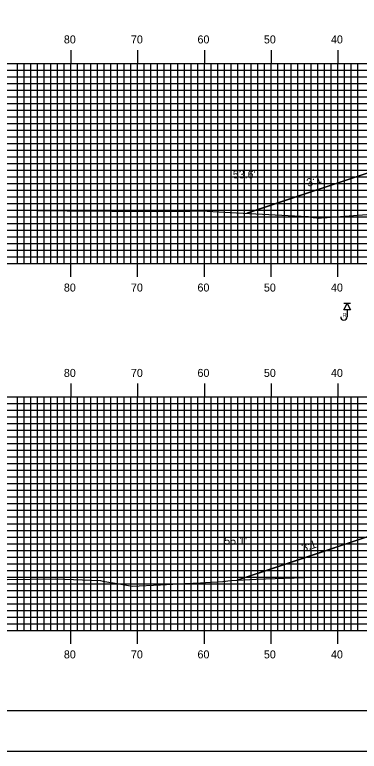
# Model space of a CAD drawing. Extents: x 1763365 to 1763708, y 442591 to 442811.
# Drawn here: x 1763442.4 to 1763494, y 442590.5 to 442701 of the extents above; entities that cross this region are included whole.
import ezdxf

# ---------------------------------------------------------------- set-up
doc = ezdxf.new("R2010")
doc.units = 0
for name, color, linetype in [('ANNOTATION', 7, 'Continuous'), ('BORDER', 7, 'Continuous'), ('BORING - REFUSAL', 7, 'Continuous'), ('D_Roadway_Centerline', 7, 'Continuous'), ('D_Roadway_SlopeLines', 7, 'Continuous'), ('D_Text_Standard', 7, 'Continuous'), ('H_V ANNOTATION', 7, 'Continuous'), ('MAJOR', 7, 'Continuous'), ('MINOR', 7, 'Continuous'), ('PLOT BOUNDARY', 7, 'Continuous'), ('S_Roadway_Centerline', 7, 'Continuous')]:
    doc.layers.add(name, color=color, linetype=linetype)

msp = doc.modelspace()

# ---------------------------------------------------------------- linework, layer by layer
at = {"layer": 'BORDER'}
msp.add_lwpolyline([(1763381.21, 442596.67), (1763701.21, 442596.67), (1763701.21, 442806.67), (1763381.21, 442806.67)], close=True, dxfattribs=at)
at = {"layer": 'BORING - REFUSAL'}
for p, q in [((1763492.69, 442657.7), (1763491.73, 442657.7)), ((1763492.21, 442656.74), (1763492.21, 442655.68))]:
    msp.add_line(p, q, dxfattribs=at)
msp.add_lwpolyline([(1763492.21, 442657.7), (1763492.69, 442656.74), (1763491.73, 442656.74)], close=True, dxfattribs=at)
msp.add_arc((1763491.72, 442655.68), 0.485, 180, 0, dxfattribs=at)
at = {"layer": 'D_Roadway_Centerline'}
for points in [[(1763477.18, 442671.2), (1763477.21, 442671.21), (1763498.81, 442678.4), (1763499.23, 442678.51), (1763499.27, 442678.52), (1763510.81, 442681.4), (1763510.81, 442681.4), (1763518.81, 442681.72), (1763519.87, 442681.76), (1763530.81, 442682.16), (1763541.63, 442682.55), (1763542.81, 442682.59), (1763550.81, 442682.27), (1763560.98, 442679.72), (1763562.81, 442679.27), (1763562.81, 442679.27), (1763576.24, 442675.91)], [(1763475.72, 442616.21), (1763481.91, 442618.27), (1763498.81, 442623.9), (1763499.25, 442624.01), (1763499.27, 442624.02), (1763502.08, 442624.72), (1763510.81, 442626.9), (1763518.81, 442627.22), (1763530.81, 442627.66), (1763542.81, 442628.09), (1763550.81, 442627.77), (1763553, 442627.22), (1763560.98, 442625.22), (1763560.98, 442625.22), (1763562.81, 442624.77), (1763562.81, 442624.77), (1763577.46, 442621.1)]]:
    msp.add_lwpolyline(points, dxfattribs=at)
at = {"layer": 'D_Roadway_SlopeLines'}
for points in [[(1763510.81, 442681.4), (1763498.81, 442678.4), (1763477.18, 442671.2)], [(1763510.81, 442626.9), (1763498.81, 442623.9), (1763475.72, 442616.21)]]:
    msp.add_lwpolyline(points, dxfattribs=at)
at = {"layer": 'MAJOR'}
for p, q in [((1763450.81, 442695.67), (1763450.81, 442693.67)), ((1763460.81, 442695.67), (1763460.81, 442693.67)), ((1763470.81, 442695.67), (1763470.81, 442693.67)), ((1763480.81, 442695.67), (1763480.81, 442693.67)), ((1763490.81, 442695.67), (1763490.81, 442693.67)), ((1763390.81, 442693.67), (1763670.81, 442693.67)), ((1763390.81, 442693.67), (1763670.81, 442693.67)), ((1763450.81, 442663.67), (1763450.81, 442693.67)), ((1763460.81, 442663.67), (1763460.81, 442693.67)), ((1763470.81, 442663.67), (1763470.81, 442693.67)), ((1763480.81, 442663.67), (1763480.81, 442693.67)), ((1763490.81, 442663.67), (1763490.81, 442693.67)), ((1763390.81, 442688.67), (1763670.81, 442688.67)), ((1763390.81, 442683.67), (1763670.81, 442683.67)), ((1763390.81, 442678.67), (1763670.81, 442678.67)), ((1763390.81, 442673.67), (1763670.81, 442673.67)), ((1763390.81, 442668.67), (1763670.81, 442668.67)), ((1763390.81, 442663.67), (1763670.81, 442663.67)), ((1763390.81, 442663.67), (1763670.81, 442663.67)), ((1763450.81, 442661.66), (1763450.81, 442663.67)), ((1763460.81, 442661.66), (1763460.81, 442663.67)), ((1763470.81, 442661.66), (1763470.81, 442663.67)), ((1763480.81, 442661.66), (1763480.81, 442663.67)), ((1763490.81, 442661.66), (1763490.81, 442663.67)), ((1763450.81, 442645.67), (1763450.81, 442643.67)), ((1763460.81, 442645.67), (1763460.81, 442643.67)), ((1763470.81, 442645.67), (1763470.81, 442643.67)), ((1763480.81, 442645.67), (1763480.81, 442643.67)), ((1763490.81, 442645.67), (1763490.81, 442643.67)), ((1763390.81, 442643.67), (1763670.81, 442643.67)), ((1763390.81, 442643.67), (1763670.81, 442643.67)), ((1763450.81, 442608.67), (1763450.81, 442643.67)), ((1763460.81, 442608.67), (1763460.81, 442643.67)), ((1763470.81, 442608.67), (1763470.81, 442643.67)), ((1763480.81, 442608.67), (1763480.81, 442643.67)), ((1763490.81, 442608.67), (1763490.81, 442643.67)), ((1763390.81, 442638.67), (1763670.81, 442638.67)), ((1763390.81, 442633.67), (1763670.81, 442633.67)), ((1763390.81, 442628.67), (1763670.81, 442628.67)), ((1763390.81, 442623.67), (1763670.81, 442623.67)), ((1763390.81, 442618.67), (1763670.81, 442618.67)), ((1763390.81, 442613.67), (1763670.81, 442613.67)), ((1763390.81, 442608.67), (1763670.81, 442608.67)), ((1763390.81, 442608.67), (1763670.81, 442608.67)), ((1763450.81, 442606.66), (1763450.81, 442608.67)), ((1763460.81, 442606.66), (1763460.81, 442608.67)), ((1763470.81, 442606.66), (1763470.81, 442608.67)), ((1763480.81, 442606.66), (1763480.81, 442608.67)), ((1763490.81, 442606.66), (1763490.81, 442608.67))]:
    msp.add_line(p, q, dxfattribs=at)
at = {"layer": 'MINOR'}
for p, q in [((1763442.81, 442663.67), (1763442.81, 442693.67)), ((1763443.81, 442663.67), (1763443.81, 442693.67)), ((1763444.81, 442663.67), (1763444.81, 442693.67)), ((1763445.81, 442663.67), (1763445.81, 442693.67)), ((1763446.81, 442663.67), (1763446.81, 442693.67)), ((1763447.81, 442663.67), (1763447.81, 442693.67)), ((1763448.81, 442663.67), (1763448.81, 442693.67)), ((1763449.81, 442663.67), (1763449.81, 442693.67)), ((1763451.81, 442663.67), (1763451.81, 442693.67)), ((1763452.81, 442663.67), (1763452.81, 442693.67)), ((1763453.81, 442663.67), (1763453.81, 442693.67)), ((1763454.81, 442663.67), (1763454.81, 442693.67)), ((1763455.81, 442663.67), (1763455.81, 442693.67)), ((1763456.81, 442663.67), (1763456.81, 442693.67)), ((1763457.81, 442663.67), (1763457.81, 442693.67)), ((1763458.81, 442663.67), (1763458.81, 442693.67)), ((1763459.81, 442663.67), (1763459.81, 442693.67)), ((1763461.81, 442663.67), (1763461.81, 442693.67)), ((1763462.81, 442663.67), (1763462.81, 442693.67)), ((1763463.81, 442663.67), (1763463.81, 442693.67)), ((1763464.81, 442663.67), (1763464.81, 442693.67)), ((1763465.81, 442663.67), (1763465.81, 442693.67)), ((1763466.81, 442663.67), (1763466.81, 442693.67)), ((1763467.81, 442663.67), (1763467.81, 442693.67)), ((1763468.81, 442663.67), (1763468.81, 442693.67)), ((1763469.81, 442663.67), (1763469.81, 442693.67)), ((1763471.81, 442663.67), (1763471.81, 442693.67)), ((1763472.81, 442663.67), (1763472.81, 442693.67)), ((1763473.81, 442663.67), (1763473.81, 442693.67)), ((1763474.81, 442663.67), (1763474.81, 442693.67)), ((1763475.81, 442663.67), (1763475.81, 442693.67)), ((1763476.81, 442663.67), (1763476.81, 442693.67)), ((1763477.81, 442663.67), (1763477.81, 442693.67)), ((1763478.81, 442663.67), (1763478.81, 442693.67)), ((1763479.81, 442663.67), (1763479.81, 442693.67)), ((1763481.81, 442663.67), (1763481.81, 442693.67)), ((1763482.81, 442663.67), (1763482.81, 442693.67)), ((1763483.81, 442663.67), (1763483.81, 442693.67)), ((1763484.81, 442663.67), (1763484.81, 442693.67)), ((1763485.81, 442663.67), (1763485.81, 442693.67)), ((1763486.81, 442663.67), (1763486.81, 442693.67)), ((1763487.81, 442663.67), (1763487.81, 442693.67)), ((1763488.81, 442663.67), (1763488.81, 442693.67)), ((1763489.81, 442663.67), (1763489.81, 442693.67)), ((1763491.81, 442663.67), (1763491.81, 442693.67)), ((1763492.81, 442663.67), (1763492.81, 442693.67)), ((1763493.81, 442663.67), (1763493.81, 442693.67)), ((1763390.81, 442692.67), (1763670.81, 442692.67)), ((1763390.81, 442691.67), (1763670.81, 442691.67)), ((1763390.81, 442690.67), (1763670.81, 442690.67)), ((1763390.81, 442689.67), (1763670.81, 442689.67)), ((1763390.81, 442687.67), (1763670.81, 442687.67)), ((1763390.81, 442686.67), (1763670.81, 442686.67)), ((1763390.81, 442685.67), (1763670.81, 442685.67)), ((1763390.81, 442684.67), (1763670.81, 442684.67)), ((1763390.81, 442682.67), (1763670.81, 442682.67)), ((1763390.81, 442681.67), (1763670.81, 442681.67)), ((1763390.81, 442680.67), (1763670.81, 442680.67)), ((1763390.81, 442679.67), (1763670.81, 442679.67)), ((1763390.81, 442677.67), (1763670.81, 442677.67)), ((1763390.81, 442676.67), (1763670.81, 442676.67)), ((1763390.81, 442675.67), (1763670.81, 442675.67)), ((1763390.81, 442674.67), (1763670.81, 442674.67)), ((1763390.81, 442672.67), (1763670.81, 442672.67)), ((1763390.81, 442671.67), (1763670.81, 442671.67)), ((1763390.81, 442670.67), (1763670.81, 442670.67)), ((1763390.81, 442669.67), (1763670.81, 442669.67)), ((1763390.81, 442667.67), (1763670.81, 442667.67)), ((1763390.81, 442666.67), (1763670.81, 442666.67)), ((1763390.81, 442665.67), (1763670.81, 442665.67)), ((1763390.81, 442664.67), (1763670.81, 442664.67)), ((1763442.81, 442608.67), (1763442.81, 442643.67)), ((1763443.81, 442608.67), (1763443.81, 442643.67)), ((1763444.81, 442608.67), (1763444.81, 442643.67)), ((1763445.81, 442608.67), (1763445.81, 442643.67)), ((1763446.81, 442608.67), (1763446.81, 442643.67)), ((1763447.81, 442608.67), (1763447.81, 442643.67)), ((1763448.81, 442608.67), (1763448.81, 442643.67)), ((1763449.81, 442608.67), (1763449.81, 442643.67)), ((1763451.81, 442608.67), (1763451.81, 442643.67)), ((1763452.81, 442608.67), (1763452.81, 442643.67)), ((1763453.81, 442608.67), (1763453.81, 442643.67)), ((1763454.81, 442608.67), (1763454.81, 442643.67)), ((1763455.81, 442608.67), (1763455.81, 442643.67)), ((1763456.81, 442608.67), (1763456.81, 442643.67)), ((1763457.81, 442608.67), (1763457.81, 442643.67)), ((1763458.81, 442608.67), (1763458.81, 442643.67)), ((1763459.81, 442608.67), (1763459.81, 442643.67)), ((1763461.81, 442608.67), (1763461.81, 442643.67)), ((1763462.81, 442608.67), (1763462.81, 442643.67)), ((1763463.81, 442608.67), (1763463.81, 442643.67)), ((1763464.81, 442608.67), (1763464.81, 442643.67)), ((1763465.81, 442608.67), (1763465.81, 442643.67)), ((1763466.81, 442608.67), (1763466.81, 442643.67)), ((1763467.81, 442608.67), (1763467.81, 442643.67)), ((1763468.81, 442608.67), (1763468.81, 442643.67)), ((1763469.81, 442608.67), (1763469.81, 442643.67)), ((1763471.81, 442608.67), (1763471.81, 442643.67)), ((1763472.81, 442608.67), (1763472.81, 442643.67)), ((1763473.81, 442608.67), (1763473.81, 442643.67)), ((1763474.81, 442608.67), (1763474.81, 442643.67)), ((1763475.81, 442608.67), (1763475.81, 442643.67)), ((1763476.81, 442608.67), (1763476.81, 442643.67)), ((1763477.81, 442608.67), (1763477.81, 442643.67)), ((1763478.81, 442608.67), (1763478.81, 442643.67)), ((1763479.81, 442608.67), (1763479.81, 442643.67)), ((1763481.81, 442608.67), (1763481.81, 442643.67)), ((1763482.81, 442608.67), (1763482.81, 442643.67)), ((1763483.81, 442608.67), (1763483.81, 442643.67)), ((1763484.81, 442608.67), (1763484.81, 442643.67)), ((1763485.81, 442608.67), (1763485.81, 442643.67)), ((1763486.81, 442608.67), (1763486.81, 442643.67)), ((1763487.81, 442608.67), (1763487.81, 442643.67)), ((1763488.81, 442608.67), (1763488.81, 442643.67)), ((1763489.81, 442608.67), (1763489.81, 442643.67)), ((1763491.81, 442608.67), (1763491.81, 442643.67)), ((1763492.81, 442608.67), (1763492.81, 442643.67)), ((1763493.81, 442608.67), (1763493.81, 442643.67)), ((1763390.81, 442642.67), (1763670.81, 442642.67)), ((1763390.81, 442641.67), (1763670.81, 442641.67)), ((1763390.81, 442640.67), (1763670.81, 442640.67)), ((1763390.81, 442639.67), (1763670.81, 442639.67)), ((1763390.81, 442637.67), (1763670.81, 442637.67)), ((1763390.81, 442636.67), (1763670.81, 442636.67)), ((1763390.81, 442635.67), (1763670.81, 442635.67)), ((1763390.81, 442634.67), (1763670.81, 442634.67)), ((1763390.81, 442632.67), (1763670.81, 442632.67)), ((1763390.81, 442631.67), (1763670.81, 442631.67)), ((1763390.81, 442630.67), (1763670.81, 442630.67)), ((1763390.81, 442629.67), (1763670.81, 442629.67)), ((1763390.81, 442627.67), (1763670.81, 442627.67)), ((1763390.81, 442626.67), (1763670.81, 442626.67)), ((1763390.81, 442625.67), (1763670.81, 442625.67)), ((1763390.81, 442624.67), (1763670.81, 442624.67)), ((1763390.81, 442622.67), (1763670.81, 442622.67)), ((1763390.81, 442621.67), (1763670.81, 442621.67)), ((1763390.81, 442620.67), (1763670.81, 442620.67)), ((1763390.81, 442619.67), (1763670.81, 442619.67)), ((1763390.81, 442617.67), (1763670.81, 442617.67)), ((1763390.81, 442616.67), (1763670.81, 442616.67)), ((1763390.81, 442615.67), (1763670.81, 442615.67)), ((1763390.81, 442614.67), (1763670.81, 442614.67)), ((1763390.81, 442612.67), (1763670.81, 442612.67)), ((1763390.81, 442611.67), (1763670.81, 442611.67)), ((1763390.81, 442610.67), (1763670.81, 442610.67)), ((1763390.81, 442609.67), (1763670.81, 442609.67))]:
    msp.add_line(p, q, dxfattribs=at)
at = {"layer": 'PLOT BOUNDARY'}
msp.add_lwpolyline([(1763365.02, 442590.55), (1763705.02, 442590.55), (1763705.02, 442810.55), (1763365.02, 442810.55)], close=True, dxfattribs=at)
at = {"layer": 'S_Roadway_Centerline'}
for points in [[(1763436.46, 442671.75), (1763445.87, 442671.61), (1763450.24, 442671.55), (1763463.58, 442671.48), (1763468.61, 442671.5), (1763470.37, 442671.56), (1763474.7, 442671.33), (1763486.26, 442670.72), (1763486.36, 442670.7), (1763486.47, 442670.68), (1763486.61, 442670.66), (1763486.76, 442670.63), (1763486.94, 442670.6), (1763487.13, 442670.58), (1763487.35, 442670.55), (1763487.89, 442670.48), (1763487.89, 442670.48), (1763487.89, 442670.48), (1763487.89, 442670.48), (1763488.34, 442670.52), (1763488.79, 442670.55), (1763489.21, 442670.59), (1763495.78, 442671.06)], [(1763441.27, 442616.31), (1763448.53, 442616.4), (1763455.23, 442616.13), (1763455.62, 442616.06), (1763456.2, 442615.96), (1763457.16, 442615.79), (1763459.99, 442615.3), (1763464.25, 442615.51), (1763467.95, 442615.7), (1763470.22, 442615.81), (1763471.73, 442615.89), (1763472.79, 442615.94), (1763473.57, 442615.98), (1763474.74, 442616.16), (1763478.57, 442616.34), (1763485.68, 442616.6), (1763492.61, 442616.67), (1763503.93, 442616.62)]]:
    msp.add_lwpolyline(points, dxfattribs=at)

# ---------------------------------------------------------------- texts
at = {"layer": 'ANNOTATION'}
for rotation, p in [(18.4347, (1763486.35, 442675.16)), (18.436, (1763485.6, 442620.41))]:
    msp.add_text('3:1', height=1.2, rotation=rotation, dxfattribs=at).set_placement(p)
at = {"layer": 'BORING - REFUSAL'}
msp.add_text('R', height=0.64, dxfattribs=at).set_placement((1763491.5, 442655.62))
at = {"layer": 'D_Text_Standard'}
for s, p in [("53.6'", (1763475.07, 442676.44)), ("55.1'", (1763473.77, 442621.51))]:
    msp.add_text(s, height=1.2, dxfattribs=at).set_placement(p)
at = {"layer": 'H_V ANNOTATION'}
for s, p in [('80', (1763449.76, 442696.67)), ('70', (1763459.81, 442696.67)), ('60', (1763469.78, 442696.67)), ('50', (1763479.73, 442696.67)), ('40', (1763489.78, 442696.67)), ('80', (1763449.76, 442659.47)), ('70', (1763459.81, 442659.47)), ('60', (1763469.78, 442659.47)), ('50', (1763479.73, 442659.47)), ('40', (1763489.78, 442659.47)), ('80', (1763449.76, 442646.67)), ('70', (1763459.81, 442646.67)), ('60', (1763469.78, 442646.67)), ('50', (1763479.73, 442646.67)), ('40', (1763489.78, 442646.67)), ('80', (1763449.76, 442604.47)), ('70', (1763459.81, 442604.47)), ('60', (1763469.78, 442604.47)), ('50', (1763479.73, 442604.47)), ('40', (1763489.78, 442604.47))]:
    msp.add_text(s, height=1.2, dxfattribs=at).set_placement(p)

doc.saveas('drawing.dxf')
